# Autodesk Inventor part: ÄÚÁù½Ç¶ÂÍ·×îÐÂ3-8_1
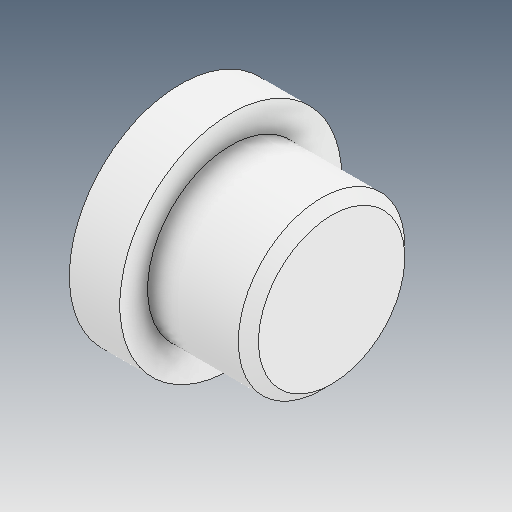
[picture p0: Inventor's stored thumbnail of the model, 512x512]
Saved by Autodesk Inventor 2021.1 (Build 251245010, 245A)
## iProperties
Created: 2021-05
Part Number: ÄÚÁù½Ç¶ÂÍ·×îÐÂ3-8_1
Material: Ogólny
Document SubType Name: Modeling
Designer: user
Density: 1 g/cm^3
Appearance: Domyślna
Author: user
Revision Number: ÈÎºÎ
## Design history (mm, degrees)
feature "ÊäÈë1"
node "Bryła1"
